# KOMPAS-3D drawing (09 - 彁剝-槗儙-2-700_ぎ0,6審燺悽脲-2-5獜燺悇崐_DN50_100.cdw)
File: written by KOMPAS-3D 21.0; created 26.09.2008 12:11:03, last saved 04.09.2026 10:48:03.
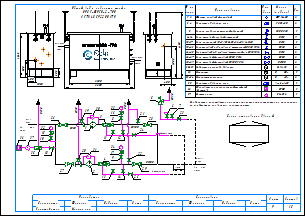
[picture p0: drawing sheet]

Sheets 1-2: A3, landscape

Document properties: Наименование: Макро:21; Автор: RaskoAdmin; Форматы листов документа: 2xA3; Полное имя файла: \\UR38nt01\Departments\КТО\КБ ПУРДГ\Заявки\Прайс-лист на типовые шкафы ГРПШ\ПРДГ_стандарт_20_03_2026\ПРДГ с РДНК\ПРДГ-ШУГО-2-700_до0,6МПа_Рвых-2-5кПа_РДНК_DN50_100.cdw

Title block, sheet 1: Наименование: Пункт учета газа / ПУГ-Ш-400-Р / ЛГТИ.485922.001ТУ; designation: ЛГТИ.03.4411141; sheet number: 1; Количество листов документа: 2; organisation: ООО "ЭЛЬСТЕР Газэлектроника"; Форматы листов документа: A3; stored path: C:\Рабочие документы\Компас\ПУГ\Схема.cdw; Разработал: Устинов; Проверил: Кошкин; Утвердил: Кошкин
Title block, sheet 2: sheet number: 2; stored path: D:\Рабочие документы\Заявки\ПУРДГ\ПУРДГ-ШУЭО-2-100-Р 4411220.cdw; designation, second copy: ЛГТИ.03.4411141-

Views: Вид 1, Вид 2
Referenced files: wcvoit.frw
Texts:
  Normal
  Вход
  газа
  PDI
  Выход
  Р=     кПа
  DN100
  DN50
  DN20
  Импульс DN15
  ≥5DN
  HYSWLongFangSong
  № на
  схеме
  Усл.
  обозн.
  Марка
  (модель)
  Кол.
  Фильтр газовый фланцевый
  ФГ 16-50
  Регулятор давления газа
  РДНК-50
  Клапан предохранительный сбросной
  КПС DN20
  Кран шаровой газовый латунный
  DN15
  Кран кнопочный VE-РАСКО-НЗ-1,6-G1/2-М20
  Кран шаровой "под приварку" штуцерный DN20 PN16
  Кран шаровой "под приварку" штуцерный п/п DN15 PN16
  Кран шаровой фланцевый DN50 PN16
  Кран шаровой фланцевый DN100 PN16
  Индикатор перепада давления
  Delta 15
  Манометр
  Манометр-напоромер
  0...     МПа
  0...     кПа
  Обогреватель газогорелочный шкафной
  (Эльтон")
  Счетчик газа
  Venio-A-15
  ОГШН
  BK-G1,6
  Общий вид и габариты шкафа
  ПРДГ-ШУГО-2-700
  Выход газа
  Вход газа
  Схема открывания дверей
  logo-rasko-ge.png
  Предприятие изготовитель может заменять комплектующие на аналогичные,
  не ухудшающие заявленных характеристик.
  Р=        МПа
  Должность
  Конструктор
  Фамилия
  Подпись
  Дата
  Согласовано
  Максимкин
  Лист
  Листов
  POLYLINE_STYLE_0.18_RGB_0_0_0
  POLYLINE_STYLE_0.50_RGB_0_0_0
  POLYLINE_STYLE_0.34_RGB_0_0_0
  PHANTOM_RGB_0_0_0_SC_1_THICK_0.18
  K5LT_THIN_RGB_0_0_0_THICK_0.18
  K5LT32769_RGB_0_0_0_THICK_0.18
  K5LT12_RGB_0_0_0_SC_1_THICK_0.18
  K5LT_DASHED_RGB_0_0_0_SC_1_THICK_0.18
  ACISOTGL_RGB_0_0_0_SC_0.8_THICK_0.25
  CONTINUOUS_RGB_0_127_31_THICK_0.3
  CONTINUOUS_RGB_0_0_255_THICK_0.35
  CONTINUOUS_RGB_255_0_0_THICK_0.35
  POLYLINE_STYLE_0.25_RGB_0_0_0
  CONTINUOUS_RGB_0_0_0_THICK_0.5
  POLYLINE_STYLE_0.35_RGB_0_0_255
  CONTINUOUS_RGB_0_0_0_THICK_0.4
  CONTINUOUS_RGB_0_0_0_THICK_0.35
  Без оформления
Dimensions and other numbers on the sheet: 1; 2; 3; 4; 5; 10; 27; 28; 29; 23; 8; 12; 18; 19; 20; 21; 22; 25; 24; 30; 31; 15; 16; 35; 36; 26; 6; 7; 11; 14; 13; 33; 1, 2; 3, 4; 6-14; 9; 15-17; 18-23; 24-25; 26-27; 28-29; 30-31; 32; 33-34; 37; 400; 1050; 500; 305; 2300; 1565; 2600; 17; 34; 1000; 4130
